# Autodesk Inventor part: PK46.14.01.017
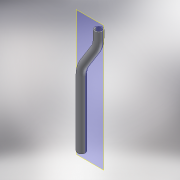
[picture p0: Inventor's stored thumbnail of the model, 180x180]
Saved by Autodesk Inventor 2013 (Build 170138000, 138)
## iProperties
Created: 2005-03
Part Number: PK46.14.01.017
Document SubType Name: Modeling
Designer: elarisa
Manufacturer: Standard
Standards Organization: Custom
Material: Steel
Mass: 411.783 g
Surface Area: 422.714 cm^2
Volume: 52.4564 cm^3
Density: 7.85 g/cm^3
Author: elarisa
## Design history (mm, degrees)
sketch "Эскиз1"
  geometry: C1 r 11 at (-14.175, -0.194); C2 r 8.5 at (-14.175, -0.194)
  constraints: 2 centre point, 1 coincident
  dimensions: "d0" = 22 diameter of C1; "d1" = 17 diameter of C2
feature "Сдвиг2" sketch "Эскиз1" dims "d15" = 0
body "Solid1"
sketch "Эскиз2"
  geometry: L1 (25.175, 0)-(3.175, 0) reference; L2 (14.175, 0)-(14.175, 192.505); L3 (4.903, 224.835)-(-26.553, 275.165); L4 (-35.825, 307.495)-(-35.825, 330); A1 r 61 centre (25.175, 307.495) between (-35.825, 307.495) and (-26.553, 275.165); A2 r 61 centre (-46.825, 192.505) between (14.175, 192.505) and (4.903, 224.835); 2 further points
  constraints: 6 end point, 4 point on circle, 4 point on line, 4 tangent, 2 centre point, 1 equal radius
  dimensions: "d3" = 210 distance of point (14.175, 210) L2.start; "d4" = 0 horizontal distance of point (14.175, 210) L2.start; "d8" = 50 horizontal distance of point (-35.825, 290) point (14.175, 210); "d9" = 80 vertical distance of point (-35.825, 290) point (14.175, 210); "d10" = 0 horizontal distance of L4.end point (-35.825, 290); "d11" = 40 distance of point (-35.825, 290) L4.end; "d14" = 61 radius of A1
